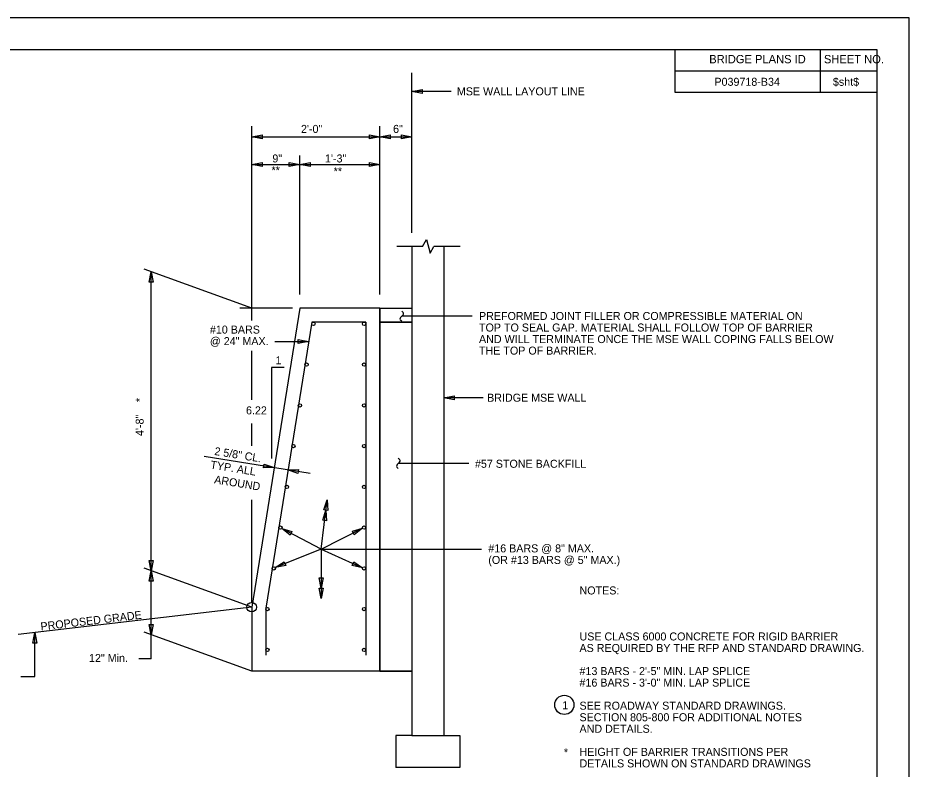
# Model space of a CAD drawing. Extents: x 96 to 240, y 601 to 689.
# Drawn here: x 184.2 to 239.8, y 642.1 to 689 of the extents above; entities that cross this region are included whole.
import ezdxf

# ---------------------------------------------------------------- set-up
doc = ezdxf.new("R2010")
doc.units = 0
for name, color, linetype in [('BR_AUTO DIMENSION', 7, 'Continuous'), ('BR_BORDER LINES', 7, 'Continuous'), ('BR_CONCRETE', 7, 'Continuous'), ('BR_REBAR', 7, 'Continuous'), ('BR_TEXT', 7, 'Continuous'), ('Level 31', 7, 'Continuous'), ('RD_XS_TieSlope', 7, 'Continuous')]:
    doc.layers.add(name, color=color, linetype=linetype)

msp = doc.modelspace()

# ---------------------------------------------------------------- linework, layer by layer
at = {"layer": 'BR_AUTO DIMENSION'}
for p, q in [((208.779, 675.573), (208.779, 685.578)), ((211.235, 684.401), (208.779, 684.401)), ((198.779, 670.105), (198.779, 682.232)), ((206.779, 671.73), (206.779, 682.232)), ((198.779, 681.566), (206.779, 681.566)), ((206.779, 681.566), (208.779, 681.566)), ((201.779, 671.73), (201.779, 680.416)), ((198.779, 679.85), (201.779, 679.85)), ((201.779, 679.85), (206.779, 679.85)), ((198.779, 670.88), (192.055, 673.316)), ((192.504, 654.486), (192.504, 673.153)), ((201.323, 670.88), (198.037, 670.88)), ((212.548, 670.386), (208.154, 670.386)), ((200.226, 668.804), (202.332, 668.804)), ((198.779, 665.164), (198.779, 668.224)), ((200.802, 667.179), (200.017, 667.179)), ((200.017, 667.179), (200.017, 661.5)), ((213.235, 665.277), (210.779, 665.277)), ((198.779, 662.281), (198.779, 663.681)), ((202.435, 660.562), (195.815, 661.626)), ((212.337, 661.192), (207.943, 661.192)), ((198.779, 652.513), (198.779, 658.909)), ((203.12, 655.842), (203.493, 658.914)), ((203.12, 655.842), (200.655, 657.123)), ((203.12, 655.842), (205.703, 657.142)), ((203.12, 655.842), (200.251, 654.684)), ((203.12, 655.842), (213.122, 655.842)), ((203.12, 655.842), (205.702, 654.67)), ((203.12, 655.842), (203.12, 652.749)), ((198.779, 652.213), (192.055, 654.649)), ((192.504, 648.989), (192.504, 654.486)), ((185.235, 647.876), (185.235, 650.623)), ((198.779, 648.213), (192.055, 650.649)), ((192.504, 648.989), (191.736, 648.989)), ((184.363, 647.876), (185.235, 647.876))]:
    msp.add_line(p, q, dxfattribs=at)
for points in [[(209.429, 684.276), (208.779, 684.401), (209.429, 684.526)], [(199.429, 681.441), (198.779, 681.566), (199.429, 681.691)], [(206.129, 681.691), (206.779, 681.566), (206.129, 681.441)], [(207.429, 681.441), (206.779, 681.566), (207.429, 681.691)], [(208.129, 681.691), (208.779, 681.566), (208.129, 681.441)], [(199.429, 679.725), (198.779, 679.85), (199.429, 679.975)], [(201.129, 679.975), (201.779, 679.85), (201.129, 679.725)], [(202.429, 679.725), (201.779, 679.85), (202.429, 679.975)], [(206.129, 679.975), (206.779, 679.85), (206.129, 679.725)], [(192.379, 672.503), (192.504, 673.153), (192.629, 672.503)], [(201.682, 668.929), (202.332, 668.804), (201.682, 668.679)], [(211.429, 665.152), (210.779, 665.277), (211.429, 665.402)], [(199.557, 661.151), (200.179, 660.925), (199.518, 660.905)], [(201.665, 660.559), (201.043, 660.786), (201.705, 660.806)], [(203.291, 658.283), (203.493, 658.914), (203.539, 658.253)], [(203.212, 657.638), (203.415, 658.268), (203.46, 657.608)], [(201.174, 656.712), (200.655, 657.123), (201.29, 656.934)], [(205.066, 656.961), (205.703, 657.142), (205.179, 656.738)], [(192.629, 655.136), (192.504, 654.486), (192.379, 655.136)], [(200.901, 654.812), (200.251, 654.684), (200.807, 655.043)], [(205.162, 655.053), (205.702, 654.67), (205.058, 654.825)], [(192.379, 653.836), (192.504, 654.486), (192.629, 653.836)], [(203.245, 654.049), (203.12, 653.399), (202.995, 654.049)], [(203.245, 653.399), (203.12, 652.749), (202.995, 653.399)], [(192.629, 651.136), (192.504, 650.486), (192.379, 651.136)], [(185.11, 649.973), (185.235, 650.623), (185.36, 649.973)]]:
    msp.add_lwpolyline(points, close=True, dxfattribs=at)
msp.add_circle((198.779, 652.213), 0.3, dxfattribs=at)
at = {"layer": 'BR_BORDER LINES'}
for p, q in [((237.837, 687.003), (103.173, 687.003)), ((225.228, 684.337), (225.228, 687.003)), ((234.293, 684.337), (234.293, 687.003)), ((237.837, 603.003), (237.837, 687.003)), ((225.228, 685.685), (237.837, 685.685)), ((234.293, 685.685), (237.837, 685.685)), ((237.837, 684.337), (225.228, 684.337))]:
    msp.add_line(p, q, dxfattribs=at)
at = {"layer": 'BR_CONCRETE'}
for p, q in [((208.779, 674.736), (208.779, 644.213)), ((210.779, 674.736), (210.779, 644.213)), ((201.779, 670.88), (198.779, 652.213)), ((206.779, 670.88), (201.779, 670.88)), ((206.779, 670.88), (208.779, 670.88)), ((206.779, 670.88), (206.779, 648.213)), ((206.779, 670.005), (208.779, 670.005)), ((198.779, 652.213), (198.779, 648.213)), ((206.779, 648.213), (198.779, 648.213)), ((206.779, 648.213), (208.779, 648.213)), ((208.779, 644.213), (207.779, 644.213)), ((207.779, 644.213), (207.779, 642.213)), ((208.779, 644.213), (210.779, 644.213)), ((210.779, 644.213), (211.779, 644.213)), ((211.779, 644.213), (211.779, 642.213)), ((211.779, 642.213), (207.779, 642.213))]:
    msp.add_line(p, q, dxfattribs=at)
at = {"layer": 'BR_REBAR'}
for p, q in [((202.525, 670.005), (199.654, 652.143)), ((205.904, 670.005), (202.525, 670.005)), ((205.904, 670.005), (205.904, 649.213)), ((199.654, 652.143), (199.654, 649.213))]:
    msp.add_line(p, q, dxfattribs=at)
for centre in [(202.629, 669.901), (205.8, 669.901), (202.203, 667.357), (205.8, 667.357), (201.795, 664.812), (205.8, 664.812), (201.386, 662.268), (205.8, 662.268), (200.977, 659.724), (205.8, 659.724), (200.568, 657.18), (205.8, 657.18), (200.159, 654.635), (205.8, 654.635), (199.758, 652.091), (205.8, 652.091), (199.758, 649.547), (205.8, 649.547)]:
    msp.add_circle(centre, 0.104, dxfattribs=at)
at = {"layer": 'BR_TEXT'}
for p, q in [((209.454, 674.736), (207.848, 674.736)), ((211.808, 674.736), (210.163, 674.736)), ((208.079, 670.304), (208.229, 670.468)), ((208.207, 670.646), (208.146, 670.688)), ((208.146, 670.071), (208.099, 670.101)), ((207.996, 661.452), (207.935, 661.495)), ((207.869, 661.111), (208.018, 661.274)), ((207.935, 660.878), (207.889, 660.907))]:
    msp.add_line(p, q, dxfattribs=at)
msp.add_lwpolyline([(209.454, 674.736), (209.701, 675.166), (209.922, 674.314), (210.163, 674.736)], dxfattribs=at)
for points in [[(206.779, 670.005), (206.779, 670.88), (208.779, 670.88), (208.779, 670.005)], [(206.779, 670.005), (208.779, 670.005), (208.779, 648.213), (206.779, 648.213)]]:
    msp.add_lwpolyline(points, close=True, dxfattribs=at)
msp.add_circle((218.305, 646.114), 0.6, dxfattribs=at)
for centre, radius, start, end in [((208.161, 670.211), 0.125, 131.007, 240.8059), ((208.154, 670.548), 0.111, 313.4519, 61.7375), ((207.943, 661.355), 0.111, 313.4519, 61.7375), ((207.95, 661.017), 0.125, 131.007, 240.8059)]:
    msp.add_arc(centre, radius, start, end, dxfattribs=at)
at = {"layer": 'Level 31'}
msp.add_line((239.84, 689.004), (95.84, 689.004), dxfattribs=at)
msp.add_lwpolyline([(95.84, 689.004), (95.84, 601.004), (239.84, 601.004), (239.84, 689.004)], dxfattribs=at)
at = {"layer": 'RD_XS_TieSlope'}
msp.add_line((198.779, 652.213), (184.192, 650.5), dxfattribs=at)

# ---------------------------------------------------------------- texts
at = {"layer": 'BR_AUTO DIMENSION'}
for s, p in [('MSE WALL LAYOUT LINE', (211.594, 684.164)), ('2\'-0"', (201.856, 681.819)), ('6"', (207.609, 681.819)), ('9"', (200.07, 679.975)), ('1\'-3"', (203.356, 679.975)), ('**', (200.016, 679.242)), ('**', (203.898, 679.179)), ('PREFORMED JOINT FILLER OR COMPRESSIBLE MATERIAL ON', (212.975, 670.141)), ('#10 BARS', (196.168, 669.292)), ('TOP TO SEAL GAP. MATERIAL SHALL FOLLOW TOP OF BARRIER', (212.975, 669.421)), ('AND WILL TERMINATE ONCE THE MSE WALL COPING FALLS BELOW ', (212.975, 668.7)), ('@ 24" MAX.', (196.168, 668.572)), ('THE TOP OF BARRIER.', (212.975, 667.98)), ('1', (200.266, 667.376)), ('BRIDGE MSE WALL', (213.481, 665.04)), ('6.22', (198.424, 664.249)), ('#57 STONE BACKFILL', (212.723, 660.916)), ('#16 BARS @ 8" MAX.', (213.556, 655.633)), ('(OR #13 BARS @ 5" MAX.)', (213.556, 654.912)), ('NOTES:', (219.251, 653.008)), ('USE CLASS 6000 CONCRETE FOR RIGID BARRIER', (219.251, 650.136)), ('AS REQUIRED BY THE RFP AND STANDARD DRAWING.', (219.251, 649.416)), ('12" Min.', (188.619, 648.789)), ('#13 BARS - 2\'-5" MIN. LAP SPLICE', (219.251, 647.975)), ('#16 BARS - 3\'-0" MIN. LAP SPLICE', (219.251, 647.254)), ('SEE ROADWAY STANDARD DRAWINGS.', (219.251, 645.814)), ('SECTION 805-800 FOR ADDITIONAL NOTES', (219.251, 645.093)), ('AND DETAILS.', (219.251, 644.373)), ('*', (218.273, 642.907)), ('HEIGHT OF BARRIER TRANSITIONS PER', (219.251, 642.932)), ('DETAILS SHOWN ON STANDARD DRAWINGS', (219.251, 642.211))]:
    msp.add_text(s, height=0.5, dxfattribs=at).set_placement(p)
for s, rotation, p in [('*', 90, (192.032, 665.012)), ('4\'-8"', 90, (192.032, 662.897)), ('2 5/8" CL.', 350.8698, (196.423, 661.721)), ('TYP. ALL', 350.8698, (196.171, 660.875)), ('AROUND', 350.8698, (196.413, 659.95)), ('PROPOSED GRADE', 6.699, (185.622, 650.753))]:
    msp.add_text(s, height=0.5, rotation=rotation, dxfattribs=at).set_placement(p)
at = {"layer": 'BR_TEXT'}
for s, height, p in [('BRIDGE PLANS ID', 0.52, (227.353, 686.166)), ('SHEET NO.', 0.52, (234.516, 686.166)), ('P039718-B34', 0.5, (227.677, 684.761)), ('$sht$', 0.5, (235.077, 684.761)), ('1', 0.5, (218.179, 645.839))]:
    msp.add_text(s, height=height, dxfattribs=at).set_placement(p)

doc.saveas('drawing.dxf')
